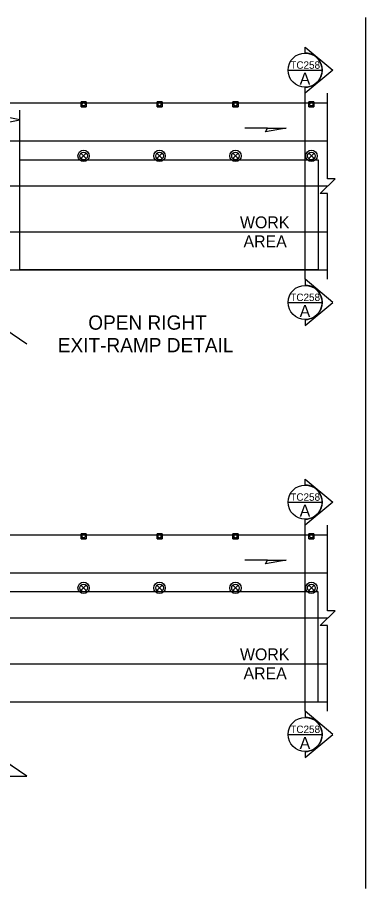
# Model space of a CAD drawing. Extents: x 99999 to 100116, y 99995 to 100013.
# Drawn here: x 100044.94 to 100047.88, y 100001.58 to 100008.92 of the extents above; entities that cross this region are included whole.
import ezdxf

# ---------------------------------------------------------------- set-up
doc = ezdxf.new("R2010")
doc.units = 0
for name, color, linetype in [('RD_MK_LineEdgeYellow', 7, 'Continuous'), ('RD_MK_LineLane', 7, 'Continuous'), ('SH_DE_DetailHeading2Text', 7, 'Continuous'), ('SH_GI_SectionCut', 7, 'Continuous'), ('TR_WZ_TrafficCone', 7, 'Continuous'), ('TR_WZ_TrafficSafetyDrum', 7, 'Continuous'), ('TR_WZ_WorkAreaLabel', 7, 'Continuous'), ('TR_WZ_WorkZoneDetails', 7, 'Continuous')]:
    doc.layers.add(name, color=color, linetype=linetype)

msp = doc.modelspace()

# ---------------------------------------------------------------- linework, layer by layer
at = {"layer": 'RD_MK_LineEdgeYellow'}
for p, q in [((100040.32, 100007.8789), (100047.555, 100007.8789)), ((100044.0968, 100007.1109), (100047.555, 100007.1109)), ((100040.32, 100004.238), (100047.555, 100004.238)), ((100044.0968, 100003.47), (100047.555, 100003.47))]:
    msp.add_line(p, q, dxfattribs=at)
at = {"layer": 'RD_MK_LineLane'}
for points in [[(100047.555, 100007.4949), (100040.32, 100007.4949)], [(100047.555, 100003.854), (100040.32, 100003.854)]]:
    msp.add_lwpolyline(points, dxfattribs=at)
at = {"layer": 'SH_GI_SectionCut'}
for p, q in [((100047.3657, 100008.6178), (100047.3657, 100008.6687)), ((100047.3657, 100008.6687), (100047.5983, 100008.4738)), ((100047.5983, 100008.4738), (100047.3657, 100008.2789)), ((100047.3657, 100008.2789), (100047.3657, 100008.3298)), ((100047.3657, 100006.7109), (100047.3657, 100008.2789)), ((100047.3657, 100006.7109), (100047.3657, 100006.66)), ((100047.5983, 100006.516), (100047.3657, 100006.7109)), ((100047.3657, 100006.3211), (100047.5983, 100006.516)), ((100047.3657, 100006.372), (100047.3657, 100006.3211)), ((100047.3657, 100004.9768), (100047.3657, 100005.0277)), ((100047.3657, 100005.0277), (100047.5983, 100004.8328)), ((100047.5983, 100004.8328), (100047.3657, 100004.638)), ((100047.3657, 100004.638), (100047.3657, 100004.6888)), ((100047.3657, 100003.0699), (100047.3657, 100004.638)), ((100047.3657, 100003.07), (100047.3657, 100003.0191)), ((100047.5983, 100002.8751), (100047.3657, 100003.07)), ((100047.3657, 100002.6802), (100047.5983, 100002.8751)), ((100047.3657, 100002.7311), (100047.3657, 100002.6802))]:
    msp.add_line(p, q, dxfattribs=at)
for points in [[(100047.2217, 100008.4738), (100047.5097, 100008.4738)], [(100047.2217, 100006.516), (100047.5097, 100006.516)], [(100047.2217, 100004.8328), (100047.5097, 100004.8328)], [(100047.2217, 100002.8751), (100047.5097, 100002.8751)]]:
    msp.add_lwpolyline(points, dxfattribs=at)
for centre in [(100047.3657, 100008.4738), (100047.3657, 100006.516), (100047.3657, 100004.8328), (100047.3657, 100002.8751)]:
    msp.add_circle(centre, 0.144, dxfattribs=at)
for centre in [(100047.3657, 100008.4738), (100047.3657, 100006.516), (100047.3657, 100004.8328), (100047.3657, 100002.8751)]:
    msp.add_arc(centre, 0.144, 269.99779, 90.00221, dxfattribs=at)
at = {"layer": 'TR_WZ_TrafficCone'}
for points in [[(100045.4776, 100008.2069), (100045.5203, 100008.2069), (100045.5203, 100008.1642), (100045.4776, 100008.1642), (100045.4776, 100008.2069)], [(100045.4776, 100008.1642), (100045.5203, 100008.1642), (100045.5203, 100008.2069), (100045.4776, 100008.2069), (100045.4776, 100008.1642)], [(100046.1176, 100008.2069), (100046.1603, 100008.2069), (100046.1603, 100008.1642), (100046.1176, 100008.1642), (100046.1176, 100008.2069)], [(100046.1176, 100008.1642), (100046.1603, 100008.1642), (100046.1603, 100008.2069), (100046.1176, 100008.2069), (100046.1176, 100008.1642)], [(100046.7576, 100008.2069), (100046.8003, 100008.2069), (100046.8003, 100008.1642), (100046.7576, 100008.1642), (100046.7576, 100008.2069)], [(100046.7576, 100008.1642), (100046.8003, 100008.1642), (100046.8003, 100008.2069), (100046.7576, 100008.2069), (100046.7576, 100008.1642)], [(100047.3976, 100008.2069), (100047.4403, 100008.2069), (100047.4403, 100008.1642), (100047.3976, 100008.1642), (100047.3976, 100008.2069)], [(100047.3976, 100008.1642), (100047.4403, 100008.1642), (100047.4403, 100008.2069), (100047.3976, 100008.2069), (100047.3976, 100008.1642)], [(100045.4776, 100004.566), (100045.5203, 100004.566), (100045.5203, 100004.5233), (100045.4776, 100004.5233), (100045.4776, 100004.566)], [(100045.4776, 100004.5233), (100045.5203, 100004.5233), (100045.5203, 100004.566), (100045.4776, 100004.566), (100045.4776, 100004.5233)], [(100046.1176, 100004.566), (100046.1603, 100004.566), (100046.1603, 100004.5233), (100046.1176, 100004.5233), (100046.1176, 100004.566)], [(100046.1176, 100004.5233), (100046.1603, 100004.5233), (100046.1603, 100004.566), (100046.1176, 100004.566), (100046.1176, 100004.5233)], [(100046.7576, 100004.566), (100046.8003, 100004.566), (100046.8003, 100004.5233), (100046.7576, 100004.5233), (100046.7576, 100004.566)], [(100046.7576, 100004.5233), (100046.8003, 100004.5233), (100046.8003, 100004.566), (100046.7576, 100004.566), (100046.7576, 100004.5233)], [(100047.3976, 100004.566), (100047.4403, 100004.566), (100047.4403, 100004.5233), (100047.3976, 100004.5233), (100047.3976, 100004.566)], [(100047.3976, 100004.5233), (100047.4403, 100004.5233), (100047.4403, 100004.566), (100047.3976, 100004.566), (100047.3976, 100004.5233)]]:
    msp.add_lwpolyline(points, dxfattribs=at)
for centre in [(100045.4989, 100008.1856), (100046.1389, 100008.1856), (100046.7789, 100008.1856), (100047.4189, 100008.1856), (100045.4989, 100004.5446), (100046.1389, 100004.5446), (100046.7789, 100004.5446), (100047.4189, 100004.5446)]:
    msp.add_circle(centre, 0.0133, dxfattribs=at)
at = {"layer": 'TR_WZ_TrafficSafetyDrum'}
for p, q in [((100045.4763, 100007.7735), (100045.5215, 100007.7283)), ((100045.5215, 100007.7735), (100045.4763, 100007.7283)), ((100046.1163, 100007.7735), (100046.1615, 100007.7283)), ((100046.1615, 100007.7735), (100046.1163, 100007.7283)), ((100046.7563, 100007.7735), (100046.8015, 100007.7283)), ((100046.8015, 100007.7735), (100046.7563, 100007.7283)), ((100047.3963, 100007.7735), (100047.4415, 100007.7283)), ((100047.4415, 100007.7735), (100047.3963, 100007.7283)), ((100045.4763, 100004.1326), (100045.5215, 100004.0873)), ((100045.5215, 100004.1326), (100045.4763, 100004.0873)), ((100046.1163, 100004.1326), (100046.1615, 100004.0873)), ((100046.1615, 100004.1326), (100046.1163, 100004.0873)), ((100046.7563, 100004.1326), (100046.8015, 100004.0873)), ((100046.8015, 100004.1326), (100046.7563, 100004.0873)), ((100047.3963, 100004.1326), (100047.4415, 100004.0873)), ((100047.4415, 100004.1326), (100047.3963, 100004.0873))]:
    msp.add_line(p, q, dxfattribs=at)
for centre, radius in [((100045.4989, 100007.7509), 0.048), ((100045.4989, 100007.7509), 0.048), ((100045.4989, 100007.7509), 0.032), ((100046.1389, 100007.7509), 0.048), ((100046.1389, 100007.7509), 0.048), ((100046.1389, 100007.7509), 0.032), ((100046.7789, 100007.7509), 0.048), ((100046.7789, 100007.7509), 0.048), ((100046.7789, 100007.7509), 0.032), ((100047.4189, 100007.7509), 0.048), ((100047.4189, 100007.7509), 0.048), ((100047.4189, 100007.7509), 0.032), ((100045.4989, 100004.11), 0.048), ((100045.4989, 100004.11), 0.048), ((100045.4989, 100004.11), 0.032), ((100046.1389, 100004.11), 0.048), ((100046.1389, 100004.11), 0.048), ((100046.1389, 100004.11), 0.032), ((100046.7789, 100004.11), 0.048), ((100046.7789, 100004.11), 0.048), ((100046.7789, 100004.11), 0.032), ((100047.4189, 100004.11), 0.048), ((100047.4189, 100004.11), 0.048), ((100047.4189, 100004.11), 0.032)]:
    msp.add_circle(centre, radius, dxfattribs=at)
at = {"layer": 'TR_WZ_WorkZoneDetails'}
for p, q in [((100047.875, 100008.9181), (100047.875, 100001.5759)), ((100040.32, 100008.1989), (100047.555, 100008.1989)), ((100040.32, 100008.1989), (100047.555, 100008.1989)), ((100044.9608, 100007.7189), (100044.9608, 100008.1373)), ((100047.0492, 100007.985), (100046.8563, 100007.985)), ((100045.0213, 100006.1639), (100044.0968, 100006.7909)), ((100044.0968, 100006.7909), (100047.555, 100006.7909)), ((100040.32, 100004.558), (100047.555, 100004.558)), ((100047.0492, 100004.344), (100046.8563, 100004.344)), ((100045.0213, 100002.523), (100044.0968, 100003.15)), ((100044.0968, 100003.15), (100047.555, 100003.15))]:
    msp.add_line(p, q, dxfattribs=at)
for points in [[(100047.555, 100006.7109), (100047.555, 100007.433), (100047.491, 100007.433), (100047.619, 100007.5569), (100047.555, 100007.5569), (100047.555, 100008.2789)], [(100047.555, 100003.07), (100047.555, 100003.792), (100047.491, 100003.792), (100047.619, 100003.9159), (100047.555, 100003.9159), (100047.555, 100004.638)]]:
    msp.add_lwpolyline(points, dxfattribs=at)
for points in [[(100044.9608, 100008.0559), (100044.8625, 100008.0751), (100044.867, 100008.0559), (100044.8625, 100008.0366)], [(100047.2065, 100007.985), (100047.0314, 100007.9541), (100047.0492, 100007.985)], [(100044.9608, 100006.7909), (100044.9608, 100007.7189), (100047.475, 100007.7189), (100047.475, 100006.7909)], [(100047.2065, 100004.344), (100047.0314, 100004.3132), (100047.0492, 100004.344)], [(100040.4, 100003.15), (100042.6438, 100003.15), (100043.5728, 100002.523), (100045.0213, 100002.523), (100044.0968, 100003.15), (100045.8504, 100003.15), (100047.475, 100003.15), (100047.475, 100004.078), (100040.4, 100004.078)]]:
    msp.add_lwpolyline(points, close=True, dxfattribs=at)

# ---------------------------------------------------------------- texts
at = {"layer": 'SH_DE_DetailHeading2Text'}
for s, p in [('OPEN RIGHT', (100045.5382, 100006.2863)), ('EXIT-RAMP DETAIL', (100045.2814, 100006.0963))]:
    msp.add_text(s, height=0.12, rotation=360, dxfattribs=at).set_placement(p)
at = {"layer": 'SH_GI_SectionCut'}
for p in [(100047.2408, 100008.4854), (100047.2408, 100006.5276), (100047.2408, 100004.8444), (100047.2408, 100002.8867)]:
    msp.add_text('TC258', height=0.0625, dxfattribs=at).set_placement(p)
for p in [(100047.3195, 100008.3518), (100047.3195, 100006.394), (100047.3195, 100004.7108), (100047.3195, 100002.7531)]:
    msp.add_text('A', height=0.1, rotation=359.99005, dxfattribs=at).set_placement(p)
at = {"layer": 'TR_WZ_WorkAreaLabel'}
for s, p in [('WORK', (100046.8169, 100007.1409)), ('AREA', (100046.8465, 100006.9809)), ('WORK', (100046.8169, 100003.5)), ('AREA', (100046.8465, 100003.34))]:
    msp.add_text(s, height=0.1, dxfattribs=at).set_placement(p)

doc.saveas('drawing.dxf')
